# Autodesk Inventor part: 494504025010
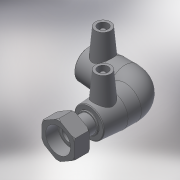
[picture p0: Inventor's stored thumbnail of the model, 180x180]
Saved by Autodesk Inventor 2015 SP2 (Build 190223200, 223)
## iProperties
Created: 2017-06
Part Number: 494504025010
Material: Generic
Description: PLASSON 90° ELBOW FEMALE FREE NUT TRANSITION 25-1"
Document SubType Name: Modeling
Designer: KIM
Mass: 55.0731 g
Surface Area: 148.067 cm^2
Volume: 55.0731 cm^3
Density: 1 g/cm^3
Appearance: Default
Author: KIM
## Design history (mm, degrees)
derived "494504.ipt"
feature "Solid1::494504.ipt"
tag "TaggingFeature1"
body "Solid1"
other parameters: "d2" = 36, "d4" = 22, "d5" = 32.4, "d8" = 168 deg, "d10" = 14.8, "d11" = 4.93333, "d29" = 38, "d30" = 15, "d31" = 36.3, "d34" = 5 deg, "d41" = 4, "d42" = 14, "d43" = 0, "d48" = 48, "d49" = 25, "d50" = 21.25, "d51" = 14.8, "d52" = 37, "d54" = 90 deg, "d57" = 25, "d58" = 37, "d59" = 0, "d61" = 90 deg, "d86" = 3, "d87" = 0, "d97" = 19, "d98" = 33, "d99" = 45.4365, "d109" = 0.75, "d116" = 16.5, "d117" = 30.291, "d118" = 13.2, "d119" = 1.32, "d120" = 24.2328, "d121" = 1.32, "d122" = 21.2037, "d123" = 19, "d124" = 1.51455, "d128" = 0, "d_" = 25, "L_" = 99, "L_1" = 37, "D_" = 19, "A_" = 38, "d_2" = 12, "L_2" = 33, "D_1" = 36, "G_" = 30.291
